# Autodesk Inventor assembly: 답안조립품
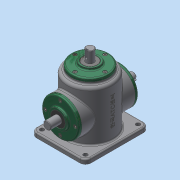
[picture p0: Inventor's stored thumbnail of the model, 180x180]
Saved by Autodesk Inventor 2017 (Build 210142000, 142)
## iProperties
Part Number: 답안조립품
Material: 일반
Document SubType Name: Assembly
Designer: MRC
Author: MRC
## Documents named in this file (16)
- C:\Users\MRC\Desktop\710116V1003\답안조립품.iam
- C:\Users\MRC\Desktop\710116V1003\본체.ipt
- C:\Users\MRC\Desktop\710116V1003\메인 베벨기어.ipt
- C:\Users\MRC\Desktop\710116V1003\메인 축.ipt
- 메인 축.ipt
- C:\Users\MRC\Desktop\710116V1003\베어링 6203.ipt
- C:\Users\MRC\Desktop\710116V1003\볼트 M4.ipt
- 볼트 M4.ipt
- C:\Users\MRC\Desktop\710116V1003\서브 베벨기어.ipt
- C:\Users\MRC\Desktop\710116V1003\서브 축.ipt
- 서브 축.ipt
- C:\Users\MRC\Desktop\710116V1003\오일 실.ipt
- 오일 실.ipt
- C:\Users\MRC\Desktop\710116V1003\커버.ipt
- C:\Users\MRC\Desktop\710116V1003\키 4x4.ipt
- C:\Users\MRC\Desktop\710116V1003\키 5x5.ipt
